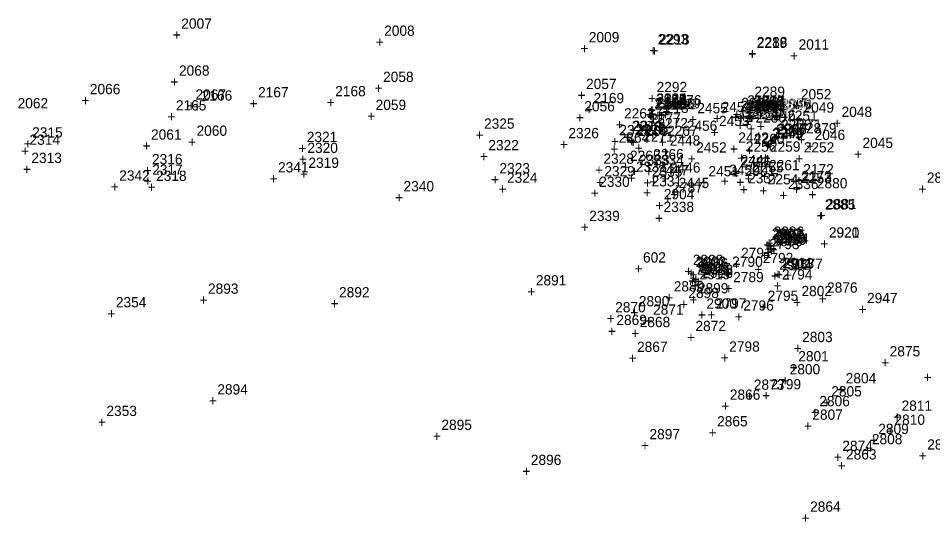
# Model space of a CAD drawing. Extents: x 2192192 to 2193475, y 863716 to 864270.
# Drawn here: x 2192506.5 to 2192729.4, y 863815.1 to 863937.9 of the extents above; entities that cross this region are included whole.
import ezdxf

# ---------------------------------------------------------------- set-up
doc = ezdxf.new("R2010")
doc.units = 0
for name, color, linetype in [('S_Bridge_Abutment_Bottom', 7, 'Continuous'), ('S_Bridge_Centerline', 7, 'Continuous'), ('S_Bridge_Curb', 7, 'Continuous'), ('S_Bridge_Deck', 7, 'Continuous'), ('S_Bridge_Fascia', 7, 'Continuous'), ('S_Bridge_Parapet', 7, 'Continuous'), ('S_Bridge_Seat', 7, 'Continuous'), ('S_Bridge_Wingwall', 7, 'Continuous'), ('S_Control_Temp_Traverse', 7, 'Continuous'), ('S_Drainage_Ditch_Line', 7, 'Continuous'), ('S_Drainage_RipRap', 7, 'Continuous'), ('S_Drainage_Waterway', 7, 'Continuous'), ('S_Ground_Elevation', 7, 'Continuous'), ('S_Ground_LevelString', 7, 'Continuous'), ('S_Ground_SpotElevation', 7, 'Continuous'), ('S_Guardrail_Beam', 7, 'Continuous'), ('S_Misc_MiscItems', 7, 'Continuous'), ('S_Roadway_Centerline', 7, 'Continuous'), ('S_Roadway_Drive_Gravel', 7, 'Continuous'), ('S_Roadway_Edge_Pavement', 7, 'Continuous'), ('S_Roadway_Edge_Shoulder', 7, 'Continuous'), ('S_Roadway_Edge_TW', 7, 'Continuous'), ('S_Trees_TreeLine', 7, 'Continuous')]:
    doc.layers.add(name, color=color, linetype=linetype)

msp = doc.modelspace()

# ---------------------------------------------------------------- texts
at = {"layer": 'S_Bridge_Abutment_Bottom'}
for s, p in [('2276', (2192665.59, 863916.63)), ('2281', (2192682.72, 863915.97)), ('2277', (2192660.52, 863912.19)), ('+', (2192663.53, 863913.88)), ('+', (2192680.66, 863913.22)), ('2280', (2192686.19, 863912.43)), ('2278', (2192657.13, 863909.35)), ('+', (2192658.46, 863909.44)), ('+', (2192684.13, 863909.68)), ('2279', (2192690.18, 863908.47)), ('+', (2192655.07, 863906.6)), ('+', (2192688.12, 863905.72))]:
    msp.add_text(s, height=2.5, dxfattribs=at).set_placement(p)
at = {"layer": 'S_Bridge_Centerline'}
for s, p in [('2218', (2192662.68, 863931.45)), ('2219', (2192686.47, 863930.63)), ('+', (2192660.62, 863928.7)), ('+', (2192684.41, 863927.88))]:
    msp.add_text(s, height=2.5, dxfattribs=at).set_placement(p)
at = {"layer": 'S_Bridge_Curb'}
for s, p in [('2222', (2192662.01, 863916.99)), ('2223', (2192685.83, 863916.51)), ('+', (2192659.95, 863914.24)), ('+', (2192683.77, 863913.76)), ('2907', (2192690.51, 863883.9)), ('2908', (2192690.9, 863883.09)), ('+', (2192688.45, 863881.15)), ('+', (2192688.83, 863880.34)), ('2906', (2192672.12, 863876.88)), ('2905', (2192672.15, 863876.05)), ('+', (2192670.06, 863874.13)), ('+', (2192670.08, 863873.3))]:
    msp.add_text(s, height=2.5, dxfattribs=at).set_placement(p)
at = {"layer": 'S_Bridge_Deck'}
for s, p in [('2214', (2192662.06, 863917.03)), ('2217', (2192685.83, 863916.53)), ('+', (2192660, 863914.28)), ('+', (2192683.77, 863913.78)), ('2901', (2192683.58, 863899.4)), ('+', (2192681.52, 863896.65)), ('2904', (2192663.85, 863893.73)), ('+', (2192661.79, 863890.98)), ('2902', (2192690.15, 863884.14)), ('+', (2192688.09, 863881.39)), ('2903', (2192671.6, 863877.25)), ('+', (2192669.54, 863874.5))]:
    msp.add_text(s, height=2.5, dxfattribs=at).set_placement(p)
at = {"layer": 'S_Bridge_Fascia'}
for s, p in [('2302', (2192662.04, 863916.12)), ('2303', (2192662.04, 863916.12)), ('2300', (2192685.84, 863915.56)), ('2301', (2192685.85, 863915.55)), ('+', (2192659.98, 863913.37)), ('+', (2192659.98, 863913.37)), ('+', (2192683.78, 863912.81)), ('+', (2192683.79, 863912.8))]:
    msp.add_text(s, height=2.5, dxfattribs=at).set_placement(p)
at = {"layer": 'S_Bridge_Parapet'}
for s, p in [('2199', (2192662, 863916.94)), ('2198', (2192662.03, 863916.12)), ('2200', (2192685.71, 863916.3)), ('2201', (2192685.85, 863915.53)), ('+', (2192659.94, 863914.19)), ('+', (2192659.97, 863913.37)), ('+', (2192683.65, 863913.55)), ('+', (2192683.79, 863912.78))]:
    msp.add_text(s, height=2.5, dxfattribs=at).set_placement(p)
at = {"layer": 'S_Bridge_Seat'}
for s, p in [('2196', (2192663.89, 863915.79)), ('2195', (2192683.72, 863915.38)), ('+', (2192661.83, 863913.04)), ('+', (2192681.66, 863912.63))]:
    msp.add_text(s, height=2.5, dxfattribs=at).set_placement(p)
at = {"layer": 'S_Bridge_Wingwall'}
for s, p in [('2210', (2192661.7, 863915.55)), ('2209', (2192661.97, 863915.87)), ('2213', (2192662.45, 863914.78)), ('2208', (2192663.48, 863915.77)), ('2202', (2192684.37, 863915.29)), ('2203', (2192685.93, 863915.24)), ('2204', (2192686.22, 863914.92)), ('+', (2192659.64, 863912.8)), ('+', (2192659.9, 863913.12)), ('+', (2192661.42, 863913.02)), ('+', (2192682.31, 863912.54)), ('2207', (2192685.39, 863914.26)), ('2211', (2192656.27, 863910.38)), ('+', (2192660.39, 863912.03)), ('+', (2192683.33, 863911.51)), ('+', (2192683.87, 863912.49)), ('+', (2192684.16, 863912.17)), ('2212', (2192657.03, 863909.58)), ('2206', (2192690.5, 863908.78)), ('2205', (2192691.23, 863909.53)), ('+', (2192654.21, 863907.63)), ('+', (2192654.97, 863906.83)), ('+', (2192688.44, 863906.03)), ('+', (2192689.17, 863906.78)), ('2909', (2192690.34, 863882.26)), ('2910', (2192691.14, 863882.62)), ('+', (2192688.28, 863879.51)), ('+', (2192689.08, 863879.87)), ('2912', (2192692.01, 863876.57)), ('2911', (2192692.76, 863876.97)), ('2916', (2192671.92, 863875.35)), ('2919', (2192672.58, 863874.21)), ('2917', (2192672.71, 863875.72)), ('2918', (2192673.29, 863874.55)), ('+', (2192669.85, 863872.6)), ('+', (2192670.65, 863872.97)), ('+', (2192689.95, 863873.82)), ('+', (2192690.7, 863874.22)), ('+', (2192670.52, 863871.46)), ('+', (2192671.23, 863871.8))]:
    msp.add_text(s, height=2.5, dxfattribs=at).set_placement(p)
at = {"layer": 'S_Control_Temp_Traverse'}
for s, p in [('602', (2192658.78, 863878.31)), ('602', (2192658.78, 863878.31)), ('602', (2192658.78, 863878.31)), ('+', (2192656.72, 863875.56)), ('+', (2192656.72, 863875.56)), ('+', (2192656.72, 863875.56))]:
    msp.add_text(s, height=2.5, dxfattribs=at).set_placement(p)
at = {"layer": 'S_Drainage_Ditch_Line'}
for s, p in [('2315', (2192509.92, 863908.79)), ('2321', (2192576.85, 863907.68)), ('+', (2192507.86, 863906.04)), ('2314', (2192509.28, 863907.01)), ('2322', (2192621.09, 863905.69)), ('+', (2192507.22, 863904.26)), ('+', (2192574.79, 863904.93)), ('2320', (2192576.99, 863905.03)), ('2316', (2192539.12, 863902.27)), ('+', (2192574.92, 863902.28)), ('+', (2192619.03, 863902.94)), ('2328', (2192649.14, 863902.39)), ('2333', (2192657.82, 863902.08)), ('2334', (2192661.28, 863902.03)), ('+', (2192537.06, 863899.52)), ('2317', (2192539.17, 863899.7)), ('2323', (2192623.8, 863900.06)), ('+', (2192647.08, 863899.64)), ('2329', (2192649.35, 863899.33)), ('+', (2192655.76, 863899.33)), ('2332', (2192657.08, 863900.43)), ('+', (2192659.22, 863899.28)), ('2335', (2192660.95, 863899.26)), ('+', (2192537.11, 863896.95)), ('+', (2192621.74, 863897.31)), ('+', (2192655.02, 863897.68)), ('+', (2192647.29, 863896.58)), ('+', (2192658.89, 863896.51))]:
    msp.add_text(s, height=2.5, dxfattribs=at).set_placement(p)
at = {"layer": 'S_Drainage_RipRap'}
for s, p in [('2262', (2192661.53, 863915.91)), ('2268', (2192664.38, 863915.68)), ('2263', (2192654.16, 863913.43)), ('+', (2192659.47, 863913.16)), ('+', (2192662.32, 863912.93)), ('2257', (2192683.58, 863913.27)), ('2258', (2192685.28, 863913.52)), ('2251', (2192693.91, 863912.87)), ('+', (2192652.1, 863910.68)), ('2270', (2192656.03, 863910.35)), ('+', (2192681.52, 863910.52)), ('+', (2192683.22, 863910.77)), ('2250', (2192692.4, 863910.67)), ('2269', (2192657.5, 863909.14)), ('2267', (2192664.65, 863909.18)), ('2249', (2192690.46, 863908.61)), ('+', (2192691.85, 863910.12)), ('2264', (2192652.86, 863907.52)), ('+', (2192653.97, 863907.6)), ('+', (2192655.44, 863906.39)), ('+', (2192662.59, 863906.43)), ('+', (2192688.4, 863905.86)), ('+', (2192690.34, 863907.92)), ('+', (2192650.8, 863904.77)), ('2266', (2192661.27, 863903.48)), ('2256', (2192683.85, 863905.32)), ('2252', (2192697.95, 863905.14)), ('2265', (2192655.62, 863903.09)), ('+', (2192681.79, 863902.57)), ('+', (2192695.89, 863902.39)), ('+', (2192653.56, 863900.34)), ('+', (2192659.21, 863900.73)), ('2255', (2192685.61, 863900.28)), ('+', (2192683.55, 863897.53)), ('2254', (2192689.19, 863897.35)), ('2253', (2192697.3, 863897.72)), ('+', (2192695.24, 863894.97)), ('+', (2192687.13, 863894.6))]:
    msp.add_text(s, height=2.5, dxfattribs=at).set_placement(p)
at = {"layer": 'S_Drainage_Waterway'}
for s, p in [('2449', (2192665.32, 863915.89)), ('2444', (2192682.43, 863915.26)), ('2443', (2192683.77, 863914.95)), ('+', (2192663.26, 863913.14)), ('+', (2192680.37, 863912.51)), ('+', (2192681.71, 863912.2)), ('2448', (2192665.31, 863906.81)), ('2442', (2192682, 863907.53)), ('+', (2192663.25, 863904.07)), ('+', (2192679.94, 863904.78)), ('2786', (2192682.55, 863901.53)), ('2441', (2192682.59, 863902)), ('2447', (2192662.44, 863899.55)), ('2446', (2192665.35, 863900.23)), ('+', (2192680.53, 863899.25)), ('+', (2192663.29, 863897.48)), ('+', (2192680.49, 863898.78)), ('+', (2192660.38, 863896.8)), ('2787', (2192665.92, 863895.37)), ('2445', (2192667.47, 863896.46)), ('+', (2192663.85, 863892.62)), ('+', (2192665.41, 863893.71)), ('2788', (2192673.31, 863875.27)), ('+', (2192671.25, 863872.52)), ('2794', (2192692.64, 863874.15)), ('+', (2192690.58, 863871.4)), ('2797', (2192676.54, 863867.08)), ('+', (2192674.48, 863864.33)), ('2798', (2192679.79, 863856.58)), ('+', (2192677.73, 863853.83)), ('2799', (2192689.87, 863847.38)), ('+', (2192687.81, 863844.63))]:
    msp.add_text(s, height=2.5, dxfattribs=at).set_placement(p)
at = {"layer": 'S_Ground_Elevation'}
for s, p in [('2245', (2192686.45, 863915.06)), ('2246', (2192688.55, 863913.02)), ('2325', (2192620.04, 863910.93)), ('+', (2192684.39, 863912.31)), ('+', (2192617.98, 863908.18)), ('2326', (2192640.59, 863908.62)), ('2327', (2192653.01, 863909.36)), ('+', (2192686.49, 863910.27)), ('2247', (2192691.54, 863909.73)), ('+', (2192638.53, 863905.87)), ('+', (2192650.95, 863906.61)), ('+', (2192689.48, 863906.98)), ('2341', (2192569.84, 863900.28)), ('2342', (2192531.14, 863898.28)), ('+', (2192567.78, 863897.53)), ('2337', (2192684.4, 863897.62)), ('+', (2192529.08, 863895.53)), ('2340', (2192600.42, 863895.66)), ('+', (2192682.34, 863894.87)), ('2336', (2192694.1, 863896.21)), ('+', (2192598.36, 863892.91)), ('+', (2192692.04, 863893.46)), ('2338', (2192663.78, 863890.63)), ('2885', (2192703.09, 863891.21)), ('2339', (2192645.68, 863888.44)), ('+', (2192701.03, 863888.46)), ('+', (2192661.72, 863887.88)), ('+', (2192643.62, 863885.69)), ('2886', (2192690.61, 863884.58)), ('2915', (2192691.03, 863883.86)), ('2920', (2192704.06, 863884.38)), ('+', (2192688.55, 863881.83)), ('2914', (2192691.72, 863882.93)), ('+', (2192702, 863881.63)), ('+', (2192688.97, 863881.11)), ('+', (2192689.66, 863880.18)), ('2888', (2192670.92, 863877.69)), ('2913', (2192693.04, 863876.86)), ('2877', (2192695.17, 863876.76)), ('+', (2192668.86, 863874.94)), ('2891', (2192632.66, 863872.73)), ('+', (2192690.98, 863874.11)), ('+', (2192693.11, 863874.01)), ('2893', (2192552.76, 863870.69)), ('2892', (2192584.7, 863869.81)), ('2889', (2192666.27, 863871.25)), ('2876', (2192703.63, 863870.97)), ('+', (2192630.6, 863869.98)), ('2890', (2192657.77, 863867.63)), ('+', (2192664.21, 863868.5)), ('+', (2192701.57, 863868.22)), ('2947', (2192713.38, 863868.4)), ('2354', (2192530.31, 863867.37)), ('+', (2192550.7, 863867.94)), ('+', (2192582.64, 863867.06)), ('2870', (2192652, 863866.17)), ('2871', (2192661.24, 863865.59)), ('+', (2192528.25, 863864.62)), ('2869', (2192652.29, 863863.07)), ('+', (2192655.71, 863864.88)), ('+', (2192711.32, 863865.65)), ('+', (2192649.94, 863863.42)), ('2868', (2192657.97, 863862.55)), ('+', (2192659.18, 863862.84)), ('2872', (2192671.56, 863861.59)), ('+', (2192650.23, 863860.32)), ('+', (2192655.91, 863859.8)), ('2867', (2192657.32, 863856.51)), ('+', (2192669.5, 863858.84)), ('2875', (2192718.89, 863855.42)), ('+', (2192655.26, 863853.76)), ('+', (2192716.83, 863852.67)), ('+', (2192727.17, 863849.08)), ('2894', (2192555.04, 863846.13)), ('2873', (2192685.79, 863847.28)), ('2866', (2192679.94, 863844.85)), ('+', (2192683.73, 863844.53)), ('2353', (2192528.01, 863840.89)), ('+', (2192552.98, 863843.38)), ('+', (2192677.88, 863842.1)), ('+', (2192525.95, 863838.14)), ('2895', (2192609.65, 863837.49)), ('2865', (2192676.84, 863838.35)), ('+', (2192607.59, 863834.74)), ('2897', (2192660.36, 863835.21)), ('+', (2192674.78, 863835.6)), ('+', (2192658.29, 863832.46)), ('2874', (2192707.35, 863832.37)), ('2863', (2192708.25, 863830.28)), ('2896', (2192631.45, 863828.94)), ('+', (2192705.29, 863829.62)), ('+', (2192629.38, 863826.19)), ('+', (2192706.18, 863827.53)), ('2864', (2192699.5, 863817.54)), ('+', (2192697.44, 863814.79))]:
    msp.add_text(s, height=2.5, dxfattribs=at).set_placement(p)
at = {"layer": 'S_Ground_LevelString'}
for s, p in [('2293', (2192662.37, 863931.53)), ('2288', (2192686.53, 863930.79)), ('+', (2192660.31, 863928.78)), ('+', (2192684.47, 863928.04)), ('2066', (2192523.98, 863919.35)), ('2292', (2192662.09, 863919.85)), ('2067', (2192549.73, 863918.04)), ('+', (2192660.02, 863917.1)), ('2291', (2192662.01, 863917.05)), ('2289', (2192685.93, 863918.71)), ('+', (2192521.92, 863916.6)), ('+', (2192547.67, 863915.29)), ('+', (2192683.87, 863915.96)), ('2290', (2192685.9, 863916.49)), ('+', (2192659.94, 863914.3)), ('+', (2192683.84, 863913.74))]:
    msp.add_text(s, height=2.5, dxfattribs=at).set_placement(p)
at = {"layer": 'S_Ground_SpotElevation'}
for s, p in [('2455', (2192672.01, 863914.7)), ('2454', (2192677.93, 863914.99)), ('2248', (2192688.49, 863915.62)), ('+', (2192686.42, 863912.87)), ('2272', (2192662.29, 863911.06)), ('2456', (2192669.45, 863910.42)), ('+', (2192669.95, 863911.95)), ('+', (2192675.87, 863912.24)), ('2453', (2192677.3, 863911.58)), ('2271', (2192658.83, 863907.76)), ('+', (2192660.23, 863908.31)), ('+', (2192675.24, 863908.83)), ('+', (2192667.39, 863907.67)), ('2260', (2192685.8, 863907.23)), ('+', (2192656.77, 863905.01)), ('2452', (2192671.73, 863905.13)), ('+', (2192683.73, 863904.48)), ('2259', (2192689.71, 863905.33)), ('+', (2192669.67, 863902.38)), ('+', (2192687.65, 863902.58)), ('2451', (2192674.73, 863899.32)), ('2450', (2192679.79, 863899.68)), ('2261', (2192689.5, 863900.81)), ('+', (2192677.73, 863896.93)), ('+', (2192687.44, 863898.06)), ('+', (2192672.67, 863896.57)), ('2792', (2192687.97, 863878.16)), ('+', (2192685.91, 863875.41)), ('2789', (2192680.75, 863873.51)), ('2899', (2192672.16, 863870.78)), ('+', (2192678.69, 863870.76)), ('2898', (2192669.83, 863869.64)), ('+', (2192670.1, 863868.03)), ('2795', (2192689.16, 863868.96)), ('+', (2192667.77, 863866.89)), ('2900', (2192674.23, 863867.05)), ('2796', (2192683.21, 863866.59)), ('+', (2192687.1, 863866.21)), ('+', (2192672.17, 863864.3)), ('+', (2192681.14, 863863.84)), ('2801', (2192696.62, 863854.21)), ('2800', (2192694.52, 863851.03)), ('+', (2192694.56, 863851.46)), ('+', (2192692.46, 863848.28)), ('2805', (2192704.66, 863845.66)), ('2806', (2192701.75, 863843.27)), ('+', (2192702.6, 863842.91)), ('+', (2192699.69, 863840.52)), ('2810', (2192720.06, 863838.74)), ('2809', (2192716.11, 863836.49)), ('+', (2192718, 863835.99)), ('+', (2192714.05, 863833.74)), ('2812', (2192728.05, 863832.69)), ('+', (2192725.99, 863829.94))]:
    msp.add_text(s, height=2.5, dxfattribs=at).set_placement(p)
at = {"layer": 'S_Guardrail_Beam'}
for s, p in [('2168', (2192583.77, 863918.85)), ('2166', (2192551.25, 863917.8)), ('2167', (2192564.97, 863918.58)), ('2169', (2192646.74, 863917.16)), ('2170', (2192684.21, 863916.58)), ('2165', (2192544.95, 863915.39)), ('+', (2192549.19, 863915.05)), ('+', (2192562.91, 863915.83)), ('+', (2192581.71, 863916.1)), ('+', (2192542.89, 863912.64)), ('+', (2192644.67, 863914.41)), ('+', (2192682.15, 863913.83)), ('2171', (2192694.91, 863910.76)), ('+', (2192692.85, 863908.01)), ('2172', (2192697.83, 863899.81)), ('+', (2192695.77, 863897.06)), ('2173', (2192697.36, 863898.14)), ('+', (2192695.3, 863895.39))]:
    msp.add_text(s, height=2.5, dxfattribs=at).set_placement(p)
at = {"layer": 'S_Misc_MiscItems'}
for s, p in [('2791', (2192682.68, 863879.41)), ('2790', (2192680.52, 863877.26)), ('+', (2192680.62, 863876.66)), ('+', (2192678.46, 863874.51))]:
    msp.add_text(s, height=2.5, dxfattribs=at).set_placement(p)
at = {"layer": 'S_Roadway_Centerline'}
for s, p in [('2007', (2192546.26, 863935.33)), ('2008', (2192595.7, 863933.59)), ('+', (2192544.2, 863932.58)), ('+', (2192593.64, 863930.84)), ('2009', (2192645.57, 863932.01)), ('2011', (2192696.7, 863930.24)), ('+', (2192643.51, 863929.26)), ('+', (2192694.63, 863927.49))]:
    msp.add_text(s, height=2.5, dxfattribs=at).set_placement(p)
at = {"layer": 'S_Roadway_Drive_Gravel'}
for s, p in [('2878', (2192692.5, 863915.68)), ('+', (2192690.44, 863912.93)), ('2879', (2192698.49, 863909.8)), ('+', (2192696.42, 863907.05)), ('2882', (2192727.95, 863897.76)), ('2880', (2192701.15, 863896.4)), ('+', (2192725.89, 863895.01)), ('+', (2192699.09, 863893.65)), ('2881', (2192703.37, 863891.32)), ('+', (2192701.31, 863888.57))]:
    msp.add_text(s, height=2.5, dxfattribs=at).set_placement(p)
at = {"layer": 'S_Roadway_Edge_Pavement'}
for s, p in [('2055', (2192661.96, 863916.96)), ('2062', (2192506.37, 863915.9)), ('2059', (2192593.62, 863915.51)), ('2056', (2192644.47, 863915.17)), ('2051', (2192686.01, 863916.42)), ('2050', (2192692.3, 863915.76)), ('2049', (2192697.89, 863914.85)), ('+', (2192591.56, 863912.76)), ('+', (2192659.89, 863914.21)), ('+', (2192683.95, 863913.67)), ('+', (2192690.24, 863913.01)), ('2048', (2192707.17, 863913.81)), ('+', (2192642.41, 863912.42)), ('+', (2192695.82, 863912.1)), ('+', (2192705.11, 863911.06)), ('2061', (2192538.88, 863908.26)), ('2060', (2192549.98, 863909.21)), ('+', (2192547.92, 863906.46)), ('+', (2192536.82, 863905.51))]:
    msp.add_text(s, height=2.5, dxfattribs=at).set_placement(p)
at = {"layer": 'S_Roadway_Edge_Shoulder'}
for s, p in [('2047', (2192692.27, 863915.5)), ('+', (2192690.21, 863912.75)), ('2046', (2192700.6, 863908.19)), ('2045', (2192712.27, 863906.24)), ('+', (2192698.54, 863905.44)), ('+', (2192710.21, 863903.5))]:
    msp.add_text(s, height=2.5, dxfattribs=at).set_placement(p)
at = {"layer": 'S_Roadway_Edge_TW'}
for s, p in [('2068', (2192545.7, 863923.87)), ('2058', (2192595.44, 863922.34)), ('+', (2192543.63, 863921.12)), ('+', (2192593.38, 863919.59)), ('2057', (2192644.9, 863920.61)), ('+', (2192642.84, 863917.86)), ('2052', (2192697.25, 863918.09)), ('+', (2192695.19, 863915.34))]:
    msp.add_text(s, height=2.5, dxfattribs=at).set_placement(p)
at = {"layer": 'S_Trees_TreeLine'}
for s, p in [('2313', (2192509.72, 863902.58)), ('2319', (2192577.24, 863901.39)), ('+', (2192507.66, 863899.83)), ('2318', (2192540.12, 863898.21)), ('+', (2192575.18, 863898.64)), ('2324', (2192625.63, 863897.75)), ('2330', (2192648.1, 863896.76)), ('2331', (2192660.87, 863896.86)), ('+', (2192538.06, 863895.46)), ('+', (2192623.57, 863895)), ('+', (2192646.03, 863894.01)), ('+', (2192658.8, 863894.11)), ('2921', (2192704.09, 863884.4)), ('2793', (2192689.51, 863881.56)), ('+', (2192702.03, 863881.65)), ('+', (2192687.45, 863878.81)), ('2802', (2192697.4, 863870.11)), ('+', (2192695.34, 863867.36)), ('2803', (2192697.56, 863858.9)), ('+', (2192695.5, 863856.15)), ('2804', (2192708.18, 863848.85)), ('+', (2192706.12, 863846.1)), ('2811', (2192721.79, 863842.16)), ('2807', (2192700.04, 863839.97)), ('+', (2192719.72, 863839.41)), ('+', (2192697.98, 863837.22)), ('2808', (2192714.56, 863834)), ('+', (2192712.5, 863831.25))]:
    msp.add_text(s, height=2.5, dxfattribs=at).set_placement(p)

doc.saveas('drawing.dxf')
